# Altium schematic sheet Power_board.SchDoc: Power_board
size A4; DocumentNumber: MB1312; Revision: A-03; SheetNumber: 8; SheetTotal: 9; Project: NUCLEO-L4P5ZG
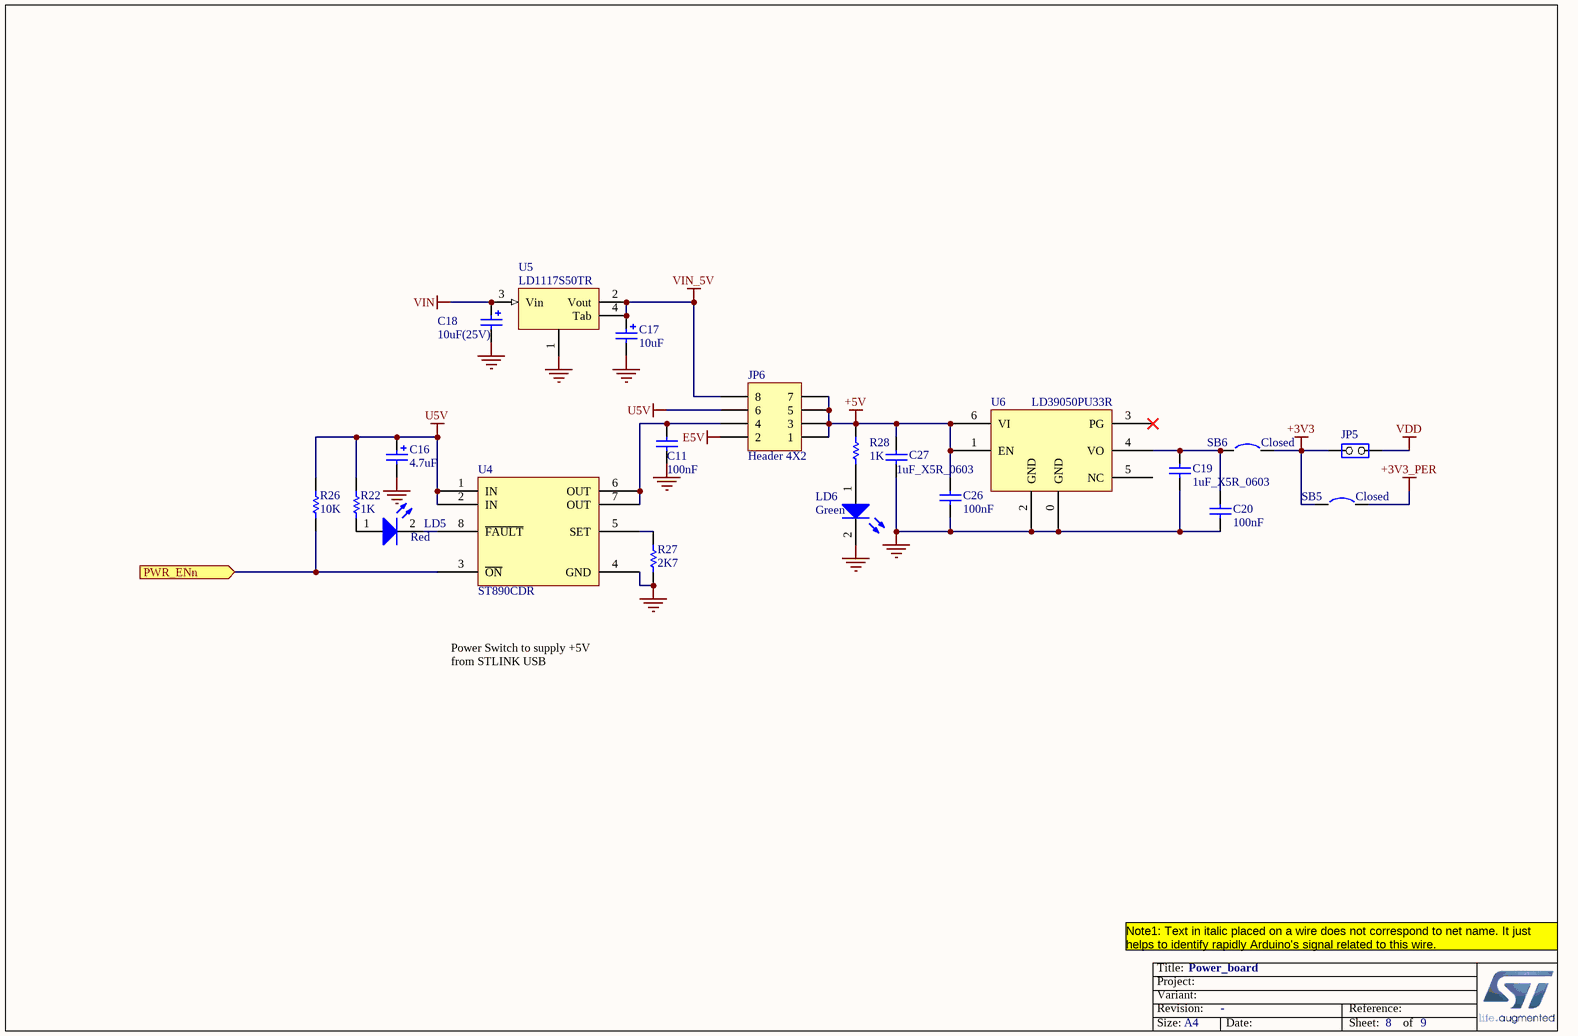
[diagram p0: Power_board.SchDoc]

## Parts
C11  100nF  [0603C]
C16  4.7uF  [TAN-A]
C17  10uF  [TAN-A]
C18  10uF(25V)  [TAN-B]
C19  1uF_X5R_0603  [0603C]
C20  100nF  [0603C]
C26  100nF  [0603C]
C27  1uF_X5R_0603  [0603C]
JP5  (no value)  [HDR_1x2_2R54_V_M_S]
JP6  Header 4X2  [HDR_4x2_2R54_V_M]
LD5  Red  [0603D-R]
LD6  Green  [0603D-G]
R22  1K  [0603R]
R26  10K  [0603R]
R27  2K7  [0603R]
R28  1K  [0603R]
SB5  Closed  [SB_0603]
SB6  Closed  [SB_0603]
U4  ST890CDR  [SOIC8_1R27_4R9X6]
U5  LD1117S50TR  [SOT-223]
U6  LD39050PU33R  [DFN6_0R95_3x3_TP]

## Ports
PWR_ENn (in)

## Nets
+3V3: JP5.1(COMMON) SB5.1 SB6.2
+3V3_PER: SB5.2
+5V: C26.2 C27.1 JP6.1 JP6.3 JP6.5 JP6.7 R28.2 U6.1(EN) U6.6(VI)
E5V: JP6.2
GND: C11.1 C16.2 C17.2 C18.2 C19.2 C20.1 C26.1 C27.2 LD6.2(K) R27.1 U4.4(GND) U5.1 U6.0(GND) U6.2(GND)
U5V: C16.1 JP6.6 R22.1 R26.1 U4.1(IN) U4.2(IN)
VDD: JP5.2(NO)
VIN: C18.1 U5.3(Vin)
VIN_5V: C17.1 JP6.8 U5.2(Vout) U5.4(Tab)
PWR_ENn: R26.2 U4.3(~{ON}) ; port PWR_ENn
NetC11_2: C11.2 JP6.4 U4.6(OUT) U4.7(OUT)
NetC19_1: C19.1 C20.2 SB6.1 U6.4(VO)
NetLD5_1: LD5.1(A) R22.2
NetLD5_2: LD5.2(K) U4.8(~{FAULT})
NetLD6_1: LD6.1(A) R28.1
NetR27_2: R27.2 U4.5(SET)

Not connected (* = marked no-connect by the designer): U6 3(PG)* 5(NC)

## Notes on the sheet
- Power Switch to supply +5V from STLINK USB
- Note1: Text in italic placed on a wire does not correspond to net name. It just helps to identify rapidly Arduino's signal related to this wire.

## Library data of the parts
C11 C20 C26 = Capacitor_ST: Capacitor 0402 / 0603 / 0805
C16 = Cap Pol1: Polarized Capacitor (Radial); Value: 100pF; Ordered by: Subcon
C17 C18 = Cap Pol1: Polarized Capacitor (Radial)
C19 C27 = CAP SMD 0603  X5R 1µF 25V 10%: 0603  X5R 1µF; Rated voltage: 25V; Tolerance: 10%
JP5 = JP2
JP6 = Header 4X2: Header, 4-Pin, Dual row
LD5 LD6 = LED2: Typical RED, GREEN, YELLOW, AMBER GaAs LED
R22 = Res1: Resistor; Ordered by: Subcon
R26 = Resistor_ST: Resistor 0402 / 0603 / 0805
R27 R28 = Resistor_ST: Resistor 0402 / 0603 / 0805; Value: 10K
SB5 SB6 = Circuit Breaker_close: Circuit Breaker
U5 = LD1117
U6 = LD39050P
